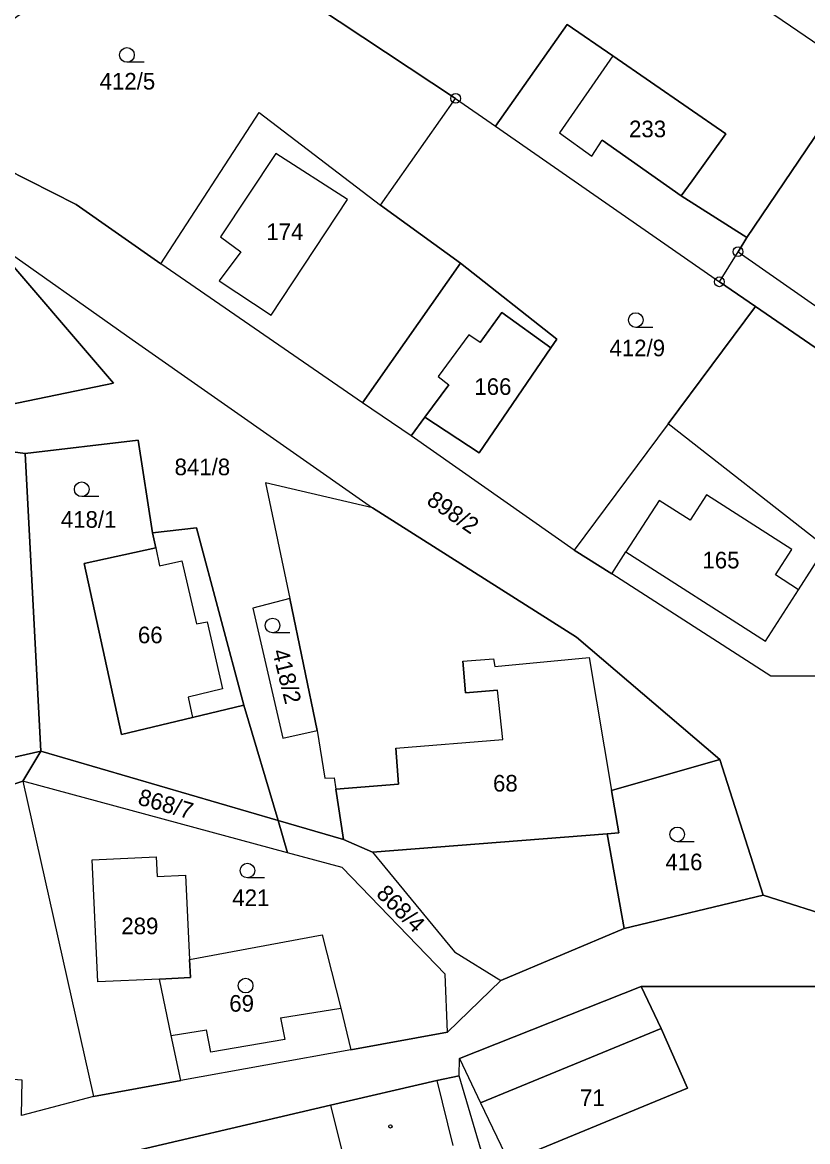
# Model space of a CAD drawing. Extents: x -654083 to -650132, y -1099819 to -1096699.
# Drawn here: x -652195.2 to -652114.8, y -1098432.3 to -1098317.8 of the extents above; entities that cross this region are included whole.
import ezdxf

# ---------------------------------------------------------------- set-up
doc = ezdxf.new("R2010")
doc.units = 0
for name, color, linetype in [('Geodetické body', 7, 'Continuous'), ('Hranice - vnitř_ kresba', 7, 'Continuous'), ('Obvody jako plochy', 7, 'Continuous'), ('Parcelní čísla', 7, 'Continuous'), ('Značky kultur', 7, 'Continuous'), ('Značky na budově ne v SPI', 7, 'Continuous')]:
    doc.layers.add(name, color=color, linetype=linetype)

msp = doc.modelspace()

# ---------------------------------------------------------------- linework, layer by layer
at = {"layer": 'Geodetické body'}
for centre, radius in [((-652150.85, -1098325.58), 0.5), ((-652150.85, -1098325.58), 0.001), ((-652121.94, -1098341.26), 0.5), ((-652121.94, -1098341.26), 0.001), ((-652123.86, -1098344.34), 0.5), ((-652123.86, -1098344.34), 0.001)]:
    msp.add_circle(centre, radius, dxfattribs=at)
at = {"layer": 'Hranice - vnitř_ kresba'}
for p, q in [((-652134.77, -1098321.21), (-652140.21, -1098329.11)), ((-652140.21, -1098329.11), (-652136.92, -1098331.47)), ((-652136.92, -1098331.47), (-652135.85, -1098329.86)), ((-652127.77, -1098335.54), (-652135.85, -1098329.86)), ((-652169.25, -1098331.21), (-652174.91, -1098339.73)), ((-652161.9, -1098335.91), (-652169.25, -1098331.21)), ((-652169.73, -1098347.76), (-652161.9, -1098335.91)), ((-652174.91, -1098339.73), (-652172.83, -1098341.26)), ((-652172.83, -1098341.26), (-652175.06, -1098344.25)), ((-652175.06, -1098344.25), (-652169.73, -1098347.76)), ((-652148.32, -1098350.56), (-652146.12, -1098347.49)), ((-652146.12, -1098347.49), (-652141.09, -1098351.08)), ((-652149.48, -1098349.75), (-652152.65, -1098354.02)), ((-652148.32, -1098350.56), (-652149.48, -1098349.75)), ((-652152.65, -1098354.02), (-652151.53, -1098354.88)), ((-652154.01, -1098358.2), (-652151.53, -1098354.88)), ((-652130.01, -1098366.73), (-652133.43, -1098371.95)), ((-652126.83, -1098368.74), (-652130.01, -1098366.73)), ((-652125.17, -1098366.14), (-652126.83, -1098368.74)), ((-652116.44, -1098371.73), (-652125.17, -1098366.14)), ((-652181.54, -1098371.57), (-652181.14, -1098373.39)), ((-652118.11, -1098374.33), (-652116.44, -1098371.73)), ((-652181.14, -1098373.39), (-652178.85, -1098372.89)), ((-652178.85, -1098372.89), (-652177.37, -1098379.33)), ((-652115.76, -1098375.84), (-652118.11, -1098374.33)), ((-652177.37, -1098379.33), (-652176.29, -1098379.13)), ((-652176.29, -1098379.13), (-652174.69, -1098385.97)), ((-652150.11, -1098383.16), (-652146.97, -1098382.91)), ((-652146.97, -1098382.91), (-652146.84, -1098383.69)), ((-652146.84, -1098383.69), (-652137.18, -1098382.77)), ((-652137.18, -1098382.77), (-652134.89, -1098396.38)), ((-652150.11, -1098383.16), (-652149.82, -1098386.38)), ((-652174.69, -1098385.97), (-652178.22, -1098386.82)), ((-652149.82, -1098386.38), (-652146.57, -1098386.12)), ((-652146.01, -1098391.15), (-652146.57, -1098386.12)), ((-652178.22, -1098386.82), (-652177.77, -1098388.9)), ((-652156.95, -1098392.06), (-652146.01, -1098391.15)), ((-652156.95, -1098392.06), (-652156.69, -1098395.72)), ((-652156.69, -1098395.72), (-652163.12, -1098396.23)), ((-652159.35, -1098402.69), (-652135.34, -1098400.81)), ((-652168.76, -1098419.64), (-652162.6, -1098418.66)), ((-652168.76, -1098419.64), (-652168.33, -1098421.85)), ((-652148.29, -1098428.35), (-652129.81, -1098420.73)), ((-652179.96, -1098421.46), (-652176.33, -1098420.87)), ((-652175.89, -1098423.14), (-652176.33, -1098420.87)), ((-652168.33, -1098421.85), (-652175.89, -1098423.14)), ((-652152.78, -1098426.05), (-652151.15, -1098432.69)), ((-652163.64, -1098428.58), (-652162.02, -1098435.12))]:
    msp.add_line(p, q, dxfattribs=at)
at = {"layer": 'Obvody jako plochy'}
for points in [[(-652096.05, -1098287.09), (-652090.93, -1098293.77), (-652094.51, -1098298.22), (-652101.62, -1098308.18), (-652088.88, -1098317.52), (-652084.95, -1098311.72), (-652079.31, -1098316.98), (-652078.19, -1098323.5), (-652079.5, -1098330.92), (-652079.11, -1098342.4), (-652109.61, -1098322.94), (-652118.18, -1098317.1)], [(-652127.77, -1098335.54), (-652121.05, -1098339.82), (-652109.61, -1098322.94), (-652118.18, -1098317.1), (-652147.98, -1098297.94), (-652152.94, -1098302.4), (-652176.99, -1098308.27), (-652150.85, -1098325.58), (-652146.77, -1098328.41), (-652139.42, -1098318), (-652134.77, -1098321.21), (-652123.19, -1098329.21), (-652126.64, -1098334.02)], [(-652181.03, -1098342.49), (-652170.94, -1098327.01), (-652158.52, -1098336.49), (-652150.85, -1098325.58), (-652176.99, -1098308.27), (-652186.79, -1098310.96), (-652202.08, -1098321.61), (-652206.66, -1098327.84), (-652189.68, -1098336.44)], [(-652121.94, -1098341.26), (-652121.05, -1098339.82), (-652127.77, -1098335.54), (-652126.64, -1098334.02), (-652123.19, -1098329.21), (-652134.77, -1098321.21), (-652139.42, -1098318), (-652146.77, -1098328.41), (-652123.86, -1098344.34)], [(-652140.21, -1098329.11), (-652136.92, -1098331.47), (-652135.85, -1098329.86), (-652127.77, -1098335.54), (-652126.64, -1098334.02), (-652123.19, -1098329.21), (-652134.77, -1098321.21)], [(-652099.08, -1098346.85), (-652086.94, -1098355.28), (-652090.48, -1098360.21), (-652091.91, -1098362.27), (-652082.29, -1098369), (-652079.11, -1098342.4), (-652109.61, -1098322.94), (-652121.05, -1098339.82), (-652121.94, -1098341.26), (-652104.06, -1098353.77)], [(-652123.86, -1098344.34), (-652120.16, -1098346.88), (-652129.08, -1098358.86), (-652138.7, -1098371.78), (-652155.4, -1098360.1), (-652154.01, -1098358.2), (-652148.45, -1098361.83), (-652141.09, -1098351.08), (-652140.49, -1098350.21), (-652150.36, -1098342.44), (-652158.52, -1098336.49), (-652150.85, -1098325.58), (-652146.77, -1098328.41)], [(-652123.82, -1098393.2), (-652119.38, -1098407.08), (-652111.42, -1098409.61), (-652113.89, -1098393.93), (-652108.27, -1098386.27), (-652112.93, -1098384.7), (-652118.58, -1098384.7), (-652134.86, -1098374.22), (-652138.7, -1098371.78), (-652155.4, -1098360.1), (-652160.37, -1098356.72), (-652181.03, -1098342.49), (-652189.68, -1098336.44), (-652206.66, -1098327.84), (-652210.39, -1098332.49), (-652198.54, -1098339.93), (-652183.96, -1098350.25), (-652159.34, -1098367.48), (-652138.48, -1098380.69)], [(-652158.52, -1098336.49), (-652150.36, -1098342.44), (-652160.37, -1098356.72), (-652181.03, -1098342.49), (-652170.94, -1098327.01)], [(-652211.78, -1098334.22), (-652210.39, -1098332.49), (-652198.54, -1098339.93), (-652185.85, -1098354.71), (-652218.2, -1098361.41), (-652222.58, -1098362.31), (-652227.46, -1098337.72), (-652216.85, -1098331.48)], [(-652172.83, -1098341.26), (-652175.06, -1098344.25), (-652169.73, -1098347.76), (-652161.9, -1098335.91), (-652169.25, -1098331.21), (-652174.91, -1098339.73)], [(-652082.29, -1098369), (-652081.69, -1098373.28), (-652120.16, -1098346.88), (-652123.86, -1098344.34), (-652121.94, -1098341.26), (-652104.06, -1098353.77), (-652100.81, -1098356.04), (-652091.91, -1098362.27)], [(-652150.36, -1098342.44), (-652140.49, -1098350.21), (-652141.09, -1098351.08), (-652148.45, -1098361.83), (-652154.01, -1098358.2), (-652155.4, -1098360.1), (-652160.37, -1098356.72)], [(-652149.48, -1098349.75), (-652152.65, -1098354.02), (-652151.53, -1098354.88), (-652154.01, -1098358.2), (-652148.45, -1098361.83), (-652141.09, -1098351.08), (-652146.12, -1098347.49), (-652148.32, -1098350.56)], [(-652081.69, -1098373.28), (-652088.59, -1098383.05), (-652097.5, -1098384.06), (-652112.97, -1098371.48), (-652129.08, -1098358.86), (-652120.16, -1098346.88)], [(-652119.14, -1098381.12), (-652115.76, -1098375.84), (-652112.97, -1098371.48), (-652129.08, -1098358.86), (-652138.7, -1098371.78), (-652134.86, -1098374.22), (-652133.43, -1098371.95)], [(-652202.83, -1098360.84), (-652194.89, -1098361.9), (-652193.31, -1098392.36), (-652208.35, -1098395.78), (-652214.63, -1098388.35), (-652206.96, -1098387.97), (-652199.2, -1098387.9), (-652199.35, -1098383.02), (-652196.71, -1098382.97), (-652196.8, -1098377.41), (-652199.52, -1098377.42), (-652199.76, -1098369.87), (-652210.12, -1098369.89), (-652210.22, -1098367.56), (-652205.96, -1098361.83)], [(-652194.89, -1098361.9), (-652183.35, -1098360.53), (-652181.87, -1098370.03), (-652181.54, -1098371.57), (-652188.85, -1098373.15), (-652185.05, -1098390.65), (-652177.77, -1098388.9), (-652172.52, -1098387.65), (-652169, -1098399.44), (-652193.31, -1098392.36)], [(-652135.34, -1098400.81), (-652134.16, -1098400.71), (-652134.89, -1098396.38), (-652123.82, -1098393.2), (-652138.48, -1098380.69), (-652159.34, -1098367.48), (-652170.29, -1098364.92), (-652167.83, -1098376.74), (-652165.02, -1098390.23), (-652164.22, -1098395.12), (-652163.27, -1098395.07), (-652163.12, -1098396.23), (-652162.32, -1098401.41), (-652159.35, -1098402.69), (-652150.96, -1098412.9), (-652146.22, -1098415.83), (-652133.6, -1098410.49)], [(-652133.43, -1098371.95), (-652119.14, -1098381.12), (-652115.76, -1098375.84), (-652118.11, -1098374.33), (-652116.44, -1098371.73), (-652125.17, -1098366.14), (-652126.83, -1098368.74), (-652130.01, -1098366.73)], [(-652177.35, -1098369.51), (-652172.52, -1098387.65), (-652177.77, -1098388.9), (-652185.05, -1098390.65), (-652188.85, -1098373.15), (-652181.54, -1098371.57), (-652181.87, -1098370.03)], [(-652178.22, -1098386.82), (-652177.77, -1098388.9), (-652185.05, -1098390.65), (-652188.85, -1098373.15), (-652181.54, -1098371.57), (-652181.14, -1098373.39), (-652178.85, -1098372.89), (-652177.37, -1098379.33), (-652176.29, -1098379.13), (-652174.69, -1098385.97)], [(-652097.5, -1098384.06), (-652112.93, -1098384.7), (-652118.58, -1098384.7), (-652134.86, -1098374.22), (-652133.43, -1098371.95), (-652119.14, -1098381.12), (-652115.76, -1098375.84), (-652112.97, -1098371.48)], [(-652165.02, -1098390.23), (-652167.83, -1098376.74), (-652171.61, -1098377.74), (-652168.54, -1098391.04)], [(-652162.32, -1098401.41), (-652163.12, -1098396.23), (-652156.69, -1098395.72), (-652156.95, -1098392.06), (-652146.01, -1098391.15), (-652146.57, -1098386.12), (-652149.82, -1098386.38), (-652150.11, -1098383.16), (-652146.97, -1098382.91), (-652146.84, -1098383.69), (-652137.18, -1098382.77), (-652134.89, -1098396.38), (-652134.16, -1098400.71), (-652135.34, -1098400.81), (-652159.35, -1098402.69)], [(-652208.35, -1098395.78), (-652193.31, -1098392.36), (-652195.15, -1098395.44), (-652207.88, -1098399.67), (-652216.78, -1098389.9), (-652216.96, -1098388.47), (-652214.63, -1098388.35)], [(-652168.04, -1098402.77), (-652195.15, -1098395.44), (-652193.31, -1098392.36), (-652169, -1098399.44)], [(-652123.82, -1098393.2), (-652134.89, -1098396.38), (-652134.16, -1098400.71), (-652135.34, -1098400.81), (-652133.6, -1098410.49), (-652119.38, -1098407.08)], [(-652195.15, -1098395.44), (-652187.92, -1098427.67), (-652195.29, -1098429.64), (-652195.22, -1098426), (-652198.18, -1098425.8), (-652197.98, -1098417.49), (-652217.58, -1098416.8), (-652217.98, -1098424.97), (-652215.01, -1098425.22), (-652215.03, -1098428.74), (-652221.7, -1098428.49), (-652223.13, -1098402.91), (-652207.88, -1098399.67)], [(-652162.47, -1098404.27), (-652168.04, -1098402.77), (-652195.15, -1098395.44), (-652187.92, -1098427.67), (-652178.98, -1098426.05), (-652179.96, -1098421.46), (-652181.15, -1098415.67), (-652187.46, -1098415.96), (-652188.04, -1098403.47), (-652181.49, -1098403.16), (-652181.4, -1098405.18), (-652178.48, -1098405.04), (-652178.08, -1098413.67), (-652164.5, -1098411.15), (-652162.6, -1098418.66), (-652161.56, -1098422.9), (-652151.69, -1098421.11), (-652151.93, -1098415.17)], [(-652162.32, -1098401.41), (-652159.35, -1098402.69), (-652150.96, -1098412.9), (-652146.22, -1098415.83), (-652151.69, -1098421.11), (-652151.93, -1098415.17), (-652162.47, -1098404.27), (-652168.04, -1098402.77), (-652169, -1098399.44)], [(-652188.04, -1098403.47), (-652181.49, -1098403.16), (-652181.4, -1098405.18), (-652178.48, -1098405.04), (-652178.08, -1098413.67), (-652177.99, -1098415.52), (-652181.15, -1098415.67), (-652187.46, -1098415.96)], [(-652178.08, -1098413.67), (-652177.99, -1098415.52), (-652181.15, -1098415.67), (-652187.46, -1098415.96), (-652188.04, -1098403.47), (-652181.49, -1098403.16), (-652181.4, -1098405.18), (-652178.48, -1098405.04)], [(-652164.5, -1098411.15), (-652162.6, -1098418.66), (-652161.56, -1098422.9), (-652178.98, -1098426.05), (-652179.96, -1098421.46), (-652181.15, -1098415.67), (-652177.99, -1098415.52), (-652178.08, -1098413.67)], [(-652145.39, -1098434.37), (-652127.11, -1098426.85), (-652129.81, -1098420.73), (-652131.87, -1098416.42), (-652150.44, -1098423.8), (-652148.29, -1098428.35)], [(-652103.52, -1098442.41), (-652106.91, -1098434.07), (-652109.86, -1098427.86), (-652111.1, -1098423.06), (-652110.52, -1098416.43), (-652131.87, -1098416.42), (-652129.81, -1098420.73), (-652127.11, -1098426.85), (-652145.39, -1098434.37), (-652140.58, -1098447.33), (-652144.19, -1098446.98), (-652141.37, -1098448.73), (-652127.94, -1098460.95), (-652118.11, -1098469.91), (-652110.62, -1098476.72), (-652094.5, -1098461.89), (-652098.68, -1098453.09)], [(-652127.11, -1098426.85), (-652129.81, -1098420.73), (-652148.29, -1098428.35), (-652145.39, -1098434.37)], [(-652150.44, -1098423.8), (-652148.29, -1098428.35), (-652145.39, -1098434.37), (-652140.58, -1098447.33), (-652144.19, -1098446.98), (-652150.49, -1098425.58)], [(-652144.19, -1098446.98), (-652150.49, -1098425.58), (-652152.78, -1098426.05), (-652163.64, -1098428.58), (-652187.85, -1098434.22), (-652177.76, -1098463.45)]]:
    msp.add_lwpolyline(points, close=True, dxfattribs=at)
for points in [[(-652218.2, -1098361.41), (-652185.85, -1098354.71), (-652198.54, -1098339.93), (-652183.96, -1098350.25), (-652159.34, -1098367.48), (-652170.29, -1098364.92), (-652167.83, -1098376.74), (-652171.61, -1098377.74), (-652168.54, -1098391.04), (-652165.02, -1098390.23), (-652164.22, -1098395.12), (-652163.27, -1098395.07), (-652163.12, -1098396.23), (-652162.32, -1098401.41), (-652169, -1098399.44), (-652172.52, -1098387.65), (-652177.35, -1098369.51), (-652181.87, -1098370.03), (-652183.35, -1098360.53), (-652194.89, -1098361.9), (-652202.83, -1098360.84)], [(-652054.22, -1098408.33), (-652061.92, -1098412.16), (-652073.35, -1098412.93), (-652081.27, -1098413.86), (-652087.67, -1098413.63), (-652096.96, -1098412.43), (-652100.59, -1098411.94), (-652111.42, -1098409.61), (-652119.38, -1098407.08), (-652133.6, -1098410.49), (-652146.22, -1098415.83), (-652151.69, -1098421.11), (-652161.56, -1098422.9)], [(-652187.85, -1098434.22), (-652163.64, -1098428.58), (-652152.78, -1098426.05), (-652150.49, -1098425.58), (-652150.44, -1098423.8), (-652131.87, -1098416.42), (-652110.52, -1098416.43), (-652085.88, -1098421.32), (-652082.73, -1098424.25), (-652083.14, -1098420.64), (-652078.41, -1098420.75), (-652071.26, -1098421.04), (-652058.9, -1098418.2), (-652037.8, -1098408.9)], [(-652161.56, -1098422.9), (-652178.98, -1098426.05), (-652187.92, -1098427.67), (-652195.29, -1098429.64)]]:
    msp.add_lwpolyline(points, dxfattribs=at)
for radius in [0.75, 0.001]:
    msp.add_circle((-652172.34, -1098416.34), radius, dxfattribs=at)
at = {"layer": 'Značky kultur'}
for p, q in [((-652182.73, -1098321.88), (-652184.48, -1098321.88)), ((-652130.66, -1098349), (-652132.41, -1098349)), ((-652187.36, -1098366.32), (-652189.11, -1098366.32)), ((-652167.83, -1098380.25), (-652169.58, -1098380.25)), ((-652126.42, -1098401.62), (-652128.17, -1098401.62)), ((-652170.4, -1098405.32), (-652172.15, -1098405.32))]:
    msp.add_line(p, q, dxfattribs=at)
for centre in [(-652184.48, -1098321.13), (-652132.41, -1098348.25), (-652189.11, -1098365.57), (-652169.58, -1098379.5), (-652128.17, -1098400.87), (-652172.15, -1098404.57)]:
    msp.add_circle(centre, 0.75, dxfattribs=at)
at = {"layer": 'Značky na budově ne v SPI'}
msp.add_circle((-652157.52, -1098430.75), 0.175, dxfattribs=at)

# ---------------------------------------------------------------- texts
at = {"layer": 'Parcelní čísla'}
for s, p in [('412/5', (-652187.28, -1098324.67)), ('233', (-652133.1, -1098329.55)), ('174', (-652170.22, -1098340.07)), ('412/9', (-652135.1, -1098351.96)), ('166', (-652148.93, -1098355.91)), ('841/8', (-652179.61, -1098364.13)), ('418/1', (-652191.25, -1098369.5)), ('165', (-652125.59, -1098373.66)), ('66', (-652183.36, -1098381.32)), ('68', (-652147.02, -1098396.49)), ('416', (-652129.38, -1098404.54)), ('421', (-652173.7, -1098408.2)), ('289', (-652185.06, -1098411.09)), ('69', (-652174.01, -1098419.01)), ('71', (-652138.12, -1098428.67))]:
    msp.add_text(s, height=1.7, dxfattribs=at).set_placement(p)
for s, rotation, p in [('898/2', 325.395, (-652153.93, -1098367)), ('418/2', 283.95, (-652169.63, -1098382.14)), ('868/7', 344.043, (-652183.47, -1098397.79)), ('868/4', 315.378, (-652159.07, -1098407.07))]:
    msp.add_text(s, height=1.7, rotation=rotation, dxfattribs=at).set_placement(p)

doc.saveas('drawing.dxf')
